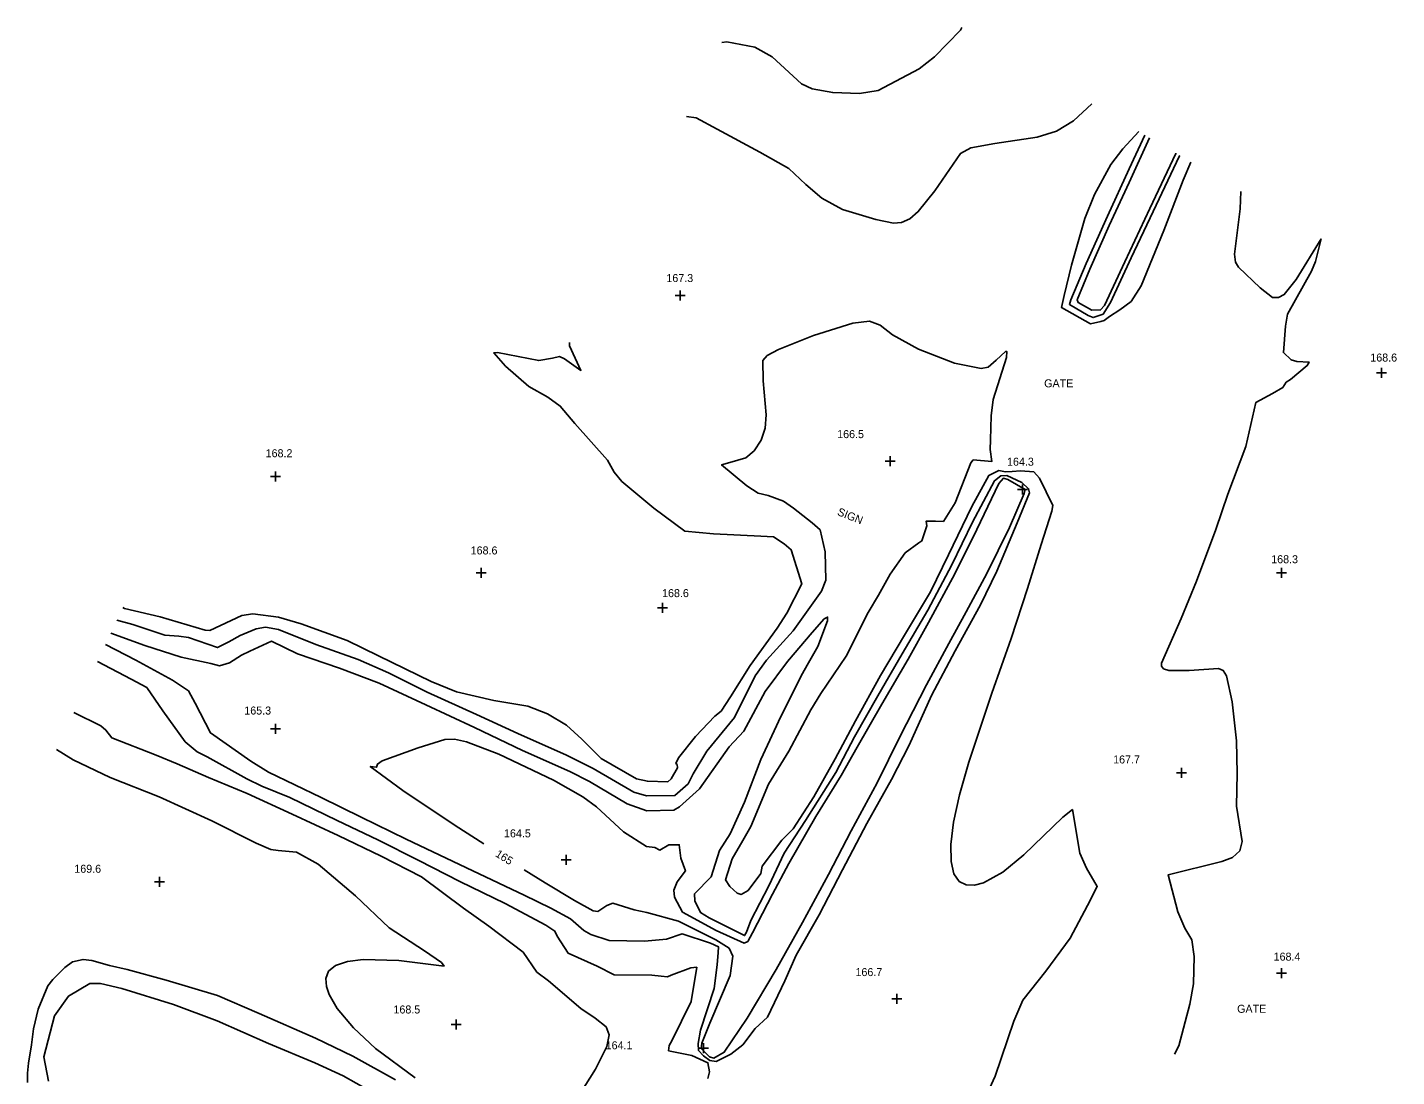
# Model space of a CAD drawing. Extents: x 1475150 to 2003689, y 770235 to 1112803.
# Drawn here: x 1998361.6 to 1998703.8, y 775974.1 to 776236.3 of the extents above; entities that cross this region are included whole.
import ezdxf

# ---------------------------------------------------------------- set-up
doc = ezdxf.new("R2010")
doc.units = 0
for name, color, linetype in [('RD_DTM_Major1', 7, 'Continuous'), ('RD_DTM_Major1_Lbl', 7, 'Continuous'), ('RD_DTM_Minor1', 7, 'Continuous'), ('RD_DTM_Spot_Elev', 7, 'Continuous'), ('RD_TX_Misc1', 7, 'Continuous')]:
    doc.layers.add(name, color=color, linetype=linetype)

msp = doc.modelspace()

# ---------------------------------------------------------------- linework, layer by layer
at = {"layer": 'RD_DTM_Major1'}
for points in [[(1998648.62, 776204.85), (1998648.6, 776204.79), (1998642.14, 776191.04), (1998635.9, 776177.72), (1998630.82, 776166.81), (1998629.82, 776165.7), (1998627.6, 776165.64), (1998624.19, 776167.53), (1998623.96, 776168.27), (1998627.13, 776175.87), (1998631.95, 776186.84), (1998636.92, 776197.58), (1998642.08, 776208.7)], [(1998475.7, 776032.25), (1998468.54, 776036.9), (1998455.5, 776045.62), (1998447.33, 776051.58), (1998448.89, 776051.43), (1998449.14, 776052.2), (1998450.32, 776053.04), (1998459.28, 776056.24), (1998465.94, 776058.38), (1998468.33, 776058.41), (1998471.34, 776057.8), (1998479.42, 776054.67), (1998493.08, 776048.2), (1998500.43, 776044.04), (1998503.82, 776041.52), (1998510.62, 776035.25), (1998516.31, 776031.59), (1998518.41, 776031.35), (1998519.67, 776030.71), (1998521.89, 776032.04), (1998524.55, 776032.07), (1998524.95, 776028.74), (1998526.06, 776025.56), (1998524.04, 776022.81), (1998523.17, 776020.7), (1998523.38, 776018.97), (1998525.35, 776015.23), (1998533.78, 776010.66), (1998540.74, 776007.44), (1998541.63, 776007.87), (1998542.86, 776010.06), (1998547.82, 776019.73), (1998551.89, 776027.38), (1998558.68, 776039.14), (1998565.03, 776049.36), (1998569.03, 776056.41), (1998575.15, 776067.23), (1998581.73, 776078.46), (1998586.81, 776087.57), (1998593.37, 776099.76), (1998598.93, 776110.84), (1998604.36, 776122.36), (1998605.56, 776123.7), (1998606.61, 776123.36), (1998610.94, 776120.82), (1998610.72, 776119.86), (1998607.05, 776111.33), (1998601.39, 776099.81), (1998596.27, 776090.25), (1998591.93, 776082.35), (1998586.31, 776072), (1998579.67, 776059.04), (1998573.96, 776047.49), (1998567.53, 776035.52), (1998561.84, 776024.66), (1998555.31, 776012.65), (1998548.74, 776000.91), (1998541.51, 775988.73), (1998535.79, 775980.2), (1998533.2, 775978.72), (1998532.1, 775979.05), (1998529.97, 775981.17), (1998530.14, 775982.49), (1998532.18, 775987.43), (1998537.29, 775999.36), (1998537.95, 776004.23), (1998537.01, 776006.2), (1998533.66, 776008.31), (1998524.35, 776012.93), (1998516.41, 776015.13), (1998513.24, 776015.79), (1998507.93, 776017.46), (1998506.41, 776016.85), (1998504.2, 776015.35), (1998503.05, 776015.58), (1998498.32, 776018.09), (1998491, 776022.53), (1998485.81, 776025.79)]]:
    msp.add_lwpolyline(points, dxfattribs=at)
at = {"layer": 'RD_DTM_Minor1'}
for points in [[(1998535.18, 776232.58), (1998536.43, 776232.68), (1998543.45, 776231.35), (1998547.74, 776228.94), (1998555.04, 776222.21), (1998557.71, 776220.97), (1998562.91, 776220.01), (1998569.54, 776219.8), (1998574.28, 776220.58), (1998584.49, 776225.99), (1998588.32, 776228.96), (1998594.78, 776235.61), (1998595.16, 776236.32)], [(1998526.35, 776214.04), (1998528.75, 776213.76), (1998534.04, 776210.87), (1998544.71, 776205.1), (1998551.92, 776201.03), (1998556.19, 776197.1), (1998560.18, 776193.61), (1998565.31, 776190.78), (1998573.62, 776188.32), (1998578.09, 776187.41), (1998580.11, 776187.59), (1998582.14, 776188.51), (1998584.26, 776190.31), (1998588.39, 776195.44), (1998594.81, 776204.81), (1998597.4, 776206.22), (1998603.4, 776207.28), (1998614.01, 776208.91), (1998618.79, 776210.41), (1998623.09, 776212.97), (1998627.67, 776217.18)], [(1998652.38, 776202.64), (1998650.49, 776198.11), (1998645.63, 776185.6), (1998639.97, 776171.73), (1998637.44, 776167.79), (1998634.59, 776165.71), (1998632.02, 776164.11), (1998630.7, 776163.05), (1998629.92, 776162.79), (1998627.28, 776162.25), (1998620.06, 776166.28), (1998620.68, 776169.32), (1998622.54, 776176.89), (1998625.87, 776188.54), (1998628.29, 776194.55), (1998632.39, 776202.07), (1998635.41, 776205.98), (1998639.39, 776210.28)], [(1998649.59, 776204.27), (1998649.55, 776204.19), (1998642.92, 776190.34), (1998637.49, 776178.7), (1998632.32, 776167.54), (1998630.46, 776164.63), (1998628, 776163.79), (1998626.68, 776164.3), (1998622.04, 776167.03), (1998622.35, 776168.23), (1998626.24, 776177.31), (1998631.51, 776189.16), (1998636.93, 776200.95), (1998640.89, 776209.4)], [(1998664.86, 776195.29), (1998664.71, 776190.95), (1998663.26, 776179.63), (1998663.53, 776177.64), (1998664.27, 776176.39), (1998669.67, 776171.26), (1998672.77, 776168.86), (1998674.26, 776168.78), (1998675.72, 776169.54), (1998678.71, 776173.29), (1998684.91, 776183.48)], [(1998684.94, 776183.47), (1998683.56, 776177.78), (1998682.54, 776175.37), (1998676.54, 776164.67), (1998676.05, 776161.68), (1998675.5, 776155.05), (1998677.44, 776153.23), (1998678.87, 776152.8), (1998681.92, 776152.68), (1998681.47, 776151.79), (1998677.29, 776148.31), (1998676.21, 776147.65), (1998675.4, 776146.33), (1998672.74, 776144.81), (1998668.64, 776142.62), (1998666.15, 776131.57), (1998661.63, 776119.7), (1998658.62, 776110.85), (1998653.78, 776097.97), (1998649.95, 776088.57), (1998645.06, 776077.46), (1998645.05, 776076.66), (1998645.56, 776075.99), (1998646.85, 776075.57), (1998651.93, 776075.64), (1998659.28, 776076.12), (1998660.49, 776075.61), (1998661.31, 776074.25), (1998662.66, 776067.81), (1998663.8, 776058.05), (1998663.97, 776049.86), (1998663.8, 776041.71), (1998665.23, 776032.9), (1998664.59, 776030.55), (1998662.78, 776028.89), (1998660.14, 776027.84), (1998646.67, 776024.52), (1998649.14, 776015.28), (1998650.85, 776011.25), (1998652.6, 776008.26), (1998653.22, 776004.11), (1998653.07, 775997.32), (1998652.08, 775992.21), (1998649.37, 775981.83), (1998648.28, 775979.75)], [(1998383.97, 776088.16), (1998387.97, 776087.12), (1998395.98, 776084.47), (1998399.46, 776084.18), (1998401.92, 776083.81), (1998409.14, 776081.35), (1998411.94, 776082.79), (1998414.79, 776084.39), (1998418.83, 776086), (1998421.17, 776086.42), (1998424.36, 776085.82), (1998433.69, 776082.09), (1998444.27, 776078.34), (1998451.86, 776075), (1998461.54, 776070.21), (1998473.85, 776064.61), (1998484.22, 776059.86), (1998496.35, 776054.41), (1998503.02, 776051.13), (1998513.22, 776045.19), (1998516.32, 776044.26), (1998523.4, 776044.35), (1998526.78, 776047.29), (1998528.04, 776049.75), (1998531.41, 776055.41), (1998538.35, 776063.82), (1998543.5, 776074.28), (1998546.33, 776078.21), (1998553.01, 776085.55), (1998560.07, 776095.39), (1998561.13, 776098.15), (1998561.01, 776105.28), (1998559.76, 776110.73), (1998557.76, 776112.48), (1998553.1, 776116.18), (1998550.56, 776117.95), (1998546.74, 776119.37), (1998544.29, 776119.96), (1998541.43, 776121.73), (1998535.13, 776127), (1998537.17, 776127.6), (1998541.13, 776128.79), (1998543.24, 776130.52), (1998544.97, 776133.16), (1998545.99, 776136.18), (1998546.24, 776139.53), (1998545.51, 776147.99), (1998545.4, 776153.06), (1998546.54, 776154.36), (1998549.31, 776155.85), (1998558.11, 776159.31), (1998567.87, 776162.42), (1998572.08, 776162.93), (1998574.76, 776161.93), (1998577.8, 776159.48), (1998584.31, 776155.89), (1998593.34, 776152.4), (1998599.94, 776151.08), (1998601.7, 776151.42), (1998603.7, 776153.13), (1998606.02, 776155.29), (1998606.43, 776155.31), (1998606.31, 776153.83), (1998602.95, 776143.3), (1998602.45, 776139.22), (1998602.32, 776133.25), (1998602.26, 776130.84), (1998602.62, 776127.8), (1998597.99, 776128.28), (1998597.41, 776127.54), (1998593.45, 776117.52), (1998590.55, 776112.87), (1998588.59, 776112.89), (1998586.2, 776112.89), (1998586.38, 776111.72), (1998585.14, 776107.97), (1998584.43, 776107.51), (1998581, 776105.02), (1998577.2, 776099.69), (1998574.29, 776094.47), (1998571.71, 776090.1), (1998566.27, 776079.22), (1998559.88, 776069.88), (1998557.38, 776065.79), (1998551.93, 776055.41), (1998546.8, 776047.19), (1998542.4, 776036.66), (1998540.4, 776033.08), (1998537.78, 776028.55), (1998536.11, 776023.25), (1998537.15, 776021.66), (1998539.03, 776019.94), (1998540.02, 776019.63), (1998541.72, 776020.65), (1998544.9, 776024.86), (1998545.25, 776026.73), (1998550.18, 776033.2), (1998552.98, 776036.07), (1998558.18, 776044.07), (1998563.48, 776053.54), (1998568.57, 776063.04), (1998574.86, 776074.32), (1998580.79, 776084.44), (1998587.32, 776095.3), (1998591.82, 776104.51), (1998597.64, 776116.57), (1998601.86, 776124.35), (1998604.4, 776125.56), (1998606.09, 776125.24), (1998607.74, 776125.37), (1998609.82, 776125.47), (1998613.14, 776125.22), (1998614.58, 776123.63), (1998617.91, 776116.88), (1998617.66, 776115.46), (1998614.95, 776107.13), (1998611.56, 776096.09), (1998607.46, 776083.56), (1998602.68, 776069.97), (1998596.88, 776052.7), (1998594.55, 776044.57), (1998593.05, 776037.69), (1998592.37, 776032.14), (1998592.44, 776027.87), (1998593.17, 776024.82), (1998594.48, 776022.91), (1998596.24, 776022.01), (1998598.33, 776021.94), (1998600.6, 776022.54), (1998605.4, 776025.24), (1998610.61, 776029.52), (1998620.39, 776038.98), (1998622.79, 776040.86), (1998624.65, 776029.92), (1998626.28, 776026.24), (1998628.99, 776021.65), (1998626.57, 776016.84), (1998622.21, 776008.72), (1998616.14, 776000.43), (1998610.35, 775993.21), (1998608.14, 775988), (1998603.45, 775974.21), (1998597.89, 775962.07)], [(1998385.47, 776091.37), (1998385.92, 776091.12), (1998394.85, 776089.05), (1998406.07, 776085.68), (1998407.25, 776085.58), (1998415.24, 776089.35), (1998417.97, 776089.75), (1998424.36, 776088.94), (1998430.07, 776087.25), (1998441.52, 776083.11), (1998449.4, 776079.31), (1998462.56, 776072.89), (1998468.88, 776070.26), (1998478.18, 776068.11), (1998486.68, 776066.71), (1998491.57, 776064.81), (1998496.39, 776061.92), (1998500.18, 776058.45), (1998505.04, 776053.65), (1998513.85, 776048.57), (1998516.57, 776047.92), (1998521.66, 776047.81), (1998522.52, 776048.55), (1998524.07, 776051.25), (1998524, 776052.1), (1998523.64, 776052.4), (1998524.38, 776053.79), (1998528.58, 776059.08), (1998533.45, 776064.19), (1998534.97, 776065.46), (1998537.31, 776069.04), (1998542.24, 776076.85), (1998548.98, 776086.18), (1998551.44, 776089.97), (1998555.15, 776097.25), (1998552.49, 776105.77), (1998550.75, 776107.25), (1998548.07, 776108.98), (1998544.93, 776109.2), (1998533.11, 776109.74), (1998525.94, 776110.39), (1998518.16, 776116.17), (1998510.2, 776122.84), (1998508.27, 776125.19), (1998506.63, 776128.13), (1998498.44, 776137.36), (1998494.8, 776141.67), (1998491.69, 776143.93), (1998486.94, 776146.57), (1998481.13, 776151.63), (1998478.16, 776154.99), (1998479.11, 776155.06), (1998489.44, 776153.05), (1998492.86, 776153.67), (1998494.65, 776154.1), (1998495.89, 776153.48), (1998499.98, 776150.59), (1998497.12, 776156.76), (1998497.08, 776157.56)], [(1998382.48, 776084.96), (1998390.98, 776081.83), (1998400.08, 776078.93), (1998407.45, 776077.33), (1998409.62, 776076.73), (1998412.16, 776077.5), (1998415.11, 776079.41), (1998417.24, 776080.41), (1998422.62, 776082.94), (1998429.18, 776079.77), (1998439.67, 776076.17), (1998449.55, 776072.45), (1998461.23, 776067.06), (1998473.37, 776061.35), (1998485.39, 776055.58), (1998497.22, 776050.39), (1998502.11, 776047.9), (1998511.49, 776042.28), (1998516.41, 776040.5), (1998523.18, 776040.74), (1998524.57, 776041.55), (1998529.57, 776046.07), (1998537.03, 776056.55), (1998540.63, 776060.45), (1998545.97, 776070.38), (1998551.55, 776077.84), (1998557.71, 776085.13), (1998560.75, 776088.53), (1998561.6, 776088.97), (1998561.61, 776088.02), (1998559.14, 776081.62), (1998556.51, 776076.94), (1998555.31, 776074.85), (1998549.94, 776064.11), (1998544.96, 776053.39), (1998540.86, 776042.7), (1998537.23, 776034.79), (1998534.57, 776030.66), (1998532.51, 776024.07), (1998528.32, 776019.76), (1998528.39, 776018.08), (1998529.86, 776015.12), (1998532, 776013.77), (1998540.87, 776009.37), (1998541.35, 776010.19), (1998542.45, 776013.13), (1998546.91, 776021.8), (1998550.73, 776029.98), (1998556.1, 776038.11), (1998563.64, 776050.09), (1998568.35, 776059), (1998574.14, 776069.3), (1998580.2, 776079.73), (1998586.62, 776090.65), (1998592.61, 776102.03), (1998597.79, 776112.67), (1998603.31, 776123.02), (1998604.86, 776124.24), (1998606.4, 776124.3), (1998610.15, 776122.59), (1998611.81, 776121.01), (1998612.09, 776120), (1998609, 776112.5), (1998603.92, 776100.46), (1998599.82, 776092), (1998593.46, 776080.53), (1998587.58, 776069.33), (1998581.95, 776056.98), (1998577.59, 776048.36), (1998571.44, 776037.36), (1998565.3, 776025.83), (1998559.49, 776014.57), (1998553.78, 776004.48), (1998550.89, 775998.09), (1998546.56, 775988.98), (1998543.52, 775986.14), (1998540.43, 775982.07), (1998537.4, 775979.7), (1998533.79, 775977.92), (1998532.17, 775978.16), (1998530.62, 775979.27), (1998529.35, 775980.68), (1998529.29, 775982.43), (1998529.87, 775985.68), (1998533.26, 775996.16), (1998534.04, 776002.06), (1998534.28, 776005.11), (1998534.31, 776006.58), (1998532.31, 776007.45), (1998525.24, 776009.83), (1998521.37, 776008.43), (1998515.81, 776008), (1998507, 776008.1), (1998502.46, 776009.64), (1998500.66, 776010.62), (1998497.37, 776013.56), (1998492.45, 776016.24), (1998485.78, 776019.44), (1998472.96, 776025.5), (1998456.31, 776033.42), (1998445.07, 776038.95), (1998435.08, 776043.86), (1998421.89, 776050.18), (1998417.48, 776052.91), (1998407.41, 776060.02), (1998403.53, 776067.41), (1998401.94, 776070.51), (1998397.94, 776073.22), (1998388.76, 776078.18), (1998381.15, 776082.1)], [(1998531.71, 775973.61), (1998532.11, 775975.33), (1998531.68, 775977.56), (1998527.66, 775979.43), (1998521.88, 775980.57), (1998522, 775981.85), (1998522.72, 775983.09), (1998527.5, 775992.86), (1998528.92, 776001.43), (1998527.44, 776001.26), (1998522.53, 775999.47), (1998521.59, 775999.05), (1998520.02, 775999.2), (1998517.7, 775999.49), (1998508.25, 775999.59), (1998504.01, 776001.69), (1998496.75, 776004.98), (1998494.06, 776009.18), (1998493.45, 776010.49), (1998491.19, 776011.98), (1998480.99, 776017.37), (1998469.7, 776022.84), (1998459.48, 776028.13), (1998449.18, 776033.3), (1998439.03, 776038.14), (1998427.26, 776043.87), (1998420.23, 776046.74), (1998416.45, 776048.5), (1998406.6, 776054.04), (1998404.06, 776055.31), (1998401.09, 776057.75), (1998395.46, 776065.51), (1998391.48, 776071.36), (1998387.59, 776073.44), (1998379.17, 776077.87)], [(1998497.36, 775966.06), (1998503.6, 775975.95), (1998506.46, 775981.63), (1998507.01, 775984.53), (1998506.3, 775986.54), (1998503.49, 775988.75), (1998499.91, 775991.17), (1998491.87, 775998.09), (1998488.96, 776000.22), (1998485.53, 776005.21), (1998476.99, 776011.74), (1998470.59, 776016.2), (1998460.14, 776024.05), (1998450.04, 776029.21), (1998439.27, 776034.33), (1998427.8, 776039.71), (1998416.58, 776044.85), (1998406.89, 776048.87), (1998399.05, 776052.31), (1998393.84, 776054.42), (1998382.72, 776058.78), (1998381.26, 776060.7), (1998379.97, 776061.78), (1998373.25, 776065.15)], [(1998458.56, 775973.85), (1998448.62, 775981.1), (1998443.14, 775986.29), (1998439.07, 775991.1), (1998437.01, 775994.63), (1998436.37, 775996.62), (1998436.25, 775998.61), (1998436.92, 776000.43), (1998438.66, 776001.91), (1998441.63, 776002.89), (1998445.53, 776003.39), (1998454.47, 776003.16), (1998465.75, 776001.75), (1998465.14, 776002.61), (1998460.91, 776005.52), (1998452.01, 776011.28), (1998443.67, 776019.28), (1998434.31, 776027.24), (1998428.93, 776030.22), (1998424.33, 776030.59), (1998422.47, 776030.91), (1998418.8, 776032.49), (1998407.74, 776038.02), (1998394.57, 776044), (1998382.35, 776048.83), (1998373.05, 776053.3), (1998368.93, 776055.87)], [(1998361.66, 775972.62), (1998361.64, 775974.97), (1998361.89, 775977.48), (1998362.64, 775982.08), (1998363.21, 775986.05), (1998364.32, 775990.95), (1998366.74, 775996.83), (1998367.98, 775998.4), (1998371, 776001.4), (1998372.92, 776002.83), (1998375.57, 776003.42), (1998377.72, 776003.17), (1998382.2, 776001.92), (1998386.55, 776000.9), (1998396.32, 775998.25), (1998409.13, 775994.35), (1998419.53, 775989.87), (1998433.65, 775983.74), (1998443, 775979.22), (1998453.61, 775973.3)], [(1998366.94, 775972.99), (1998365.72, 775979.04), (1998368.45, 775989.32), (1998371.91, 775994.22), (1998377.23, 775997.37), (1998379.92, 775997.36), (1998385.23, 775996.17), (1998398.17, 775992.14), (1998409.07, 775988.02), (1998421.88, 775982.42), (1998433.5, 775977.55), (1998440.56, 775974.3), (1998447.08, 775970.63)]]:
    msp.add_lwpolyline(points, dxfattribs=at)
at = {"layer": 'RD_DTM_Spot_Elev'}
for p, q in [((1998523.49, 776169.3), (1998525.99, 776169.3)), ((1998524.74, 776168.05), (1998524.74, 776170.55)), ((1998700, 776148.75), (1998700, 776151.25)), ((1998698.75, 776150), (1998701.25, 776150)), ((1998575.97, 776127.9), (1998578.47, 776127.9)), ((1998577.22, 776126.65), (1998577.22, 776129.15)), ((1998422.36, 776124.12), (1998424.86, 776124.12)), ((1998423.61, 776122.87), (1998423.61, 776125.37)), ((1998609.04, 776120.83), (1998611.54, 776120.83)), ((1998610.29, 776119.58), (1998610.29, 776122.08)), ((1998473.75, 776100), (1998476.25, 776100)), ((1998475, 776098.75), (1998475, 776101.25)), ((1998673.75, 776100), (1998676.25, 776100)), ((1998675, 776098.75), (1998675, 776101.25)), ((1998520.36, 776090.04), (1998520.36, 776092.54)), ((1998519.11, 776091.29), (1998521.61, 776091.29)), ((1998423.62, 776059.8), (1998423.62, 776062.3)), ((1998422.37, 776061.05), (1998424.87, 776061.05)), ((1998650.05, 776048.8), (1998650.05, 776051.3)), ((1998648.8, 776050.05), (1998651.3, 776050.05)), ((1998495.05, 776028.32), (1998497.55, 776028.32)), ((1998496.3, 776027.07), (1998496.3, 776029.57)), ((1998394.64, 776021.5), (1998394.64, 776024)), ((1998393.39, 776022.75), (1998395.89, 776022.75)), ((1998673.75, 776000), (1998676.25, 776000)), ((1998675, 775998.75), (1998675, 776001.25)), ((1998577.68, 775993.52), (1998580.18, 775993.52)), ((1998578.93, 775992.27), (1998578.93, 775994.77)), ((1998467.55, 775987.13), (1998470.05, 775987.13)), ((1998468.8, 775985.88), (1998468.8, 775988.38)), ((1998530.58, 775980.01), (1998530.58, 775982.51)), ((1998529.33, 775981.26), (1998531.83, 775981.26))]:
    msp.add_line(p, q, dxfattribs=at)

# ---------------------------------------------------------------- texts
at = {"layer": 'RD_DTM_Major1_Lbl'}
msp.add_text('165', height=2, rotation=327.7974, dxfattribs=at).set_placement((1998478.4, 776029.28))
at = {"layer": 'RD_DTM_Spot_Elev'}
for s, p in [('167.3', (1998521.32, 776172.68)), ('168.6', (1998697.22, 776152.81)), ('166.5', (1998564, 776133.68)), ('168.2', (1998421.18, 776128.9)), ('164.3', (1998606.44, 776126.78)), ('168.6', (1998472.41, 776104.61)), ('168.3', (1998672.46, 776102.41)), ('168.6', (1998520.24, 776093.94)), ('165.3', (1998415.85, 776064.6)), ('167.7', (1998632.96, 776052.37)), ('164.5', (1998480.74, 776033.91)), ('169.6', (1998373.37, 776025.06)), ('168.4', (1998673.06, 776003.1)), ('166.7', (1998568.57, 775999.24)), ('168.5', (1998453.12, 775989.89)), ('164.1', (1998506.14, 775980.94))]:
    msp.add_text(s, height=2, dxfattribs=at).set_placement(p)
at = {"layer": 'RD_TX_Misc1'}
for p in [(1998615.72, 776146.37), (1998663.94, 775990.06)]:
    msp.add_text('GATE', height=2, dxfattribs=at).set_placement(p)
msp.add_text('SIGN', height=2, rotation=338.45, dxfattribs=at).set_placement((1998563.87, 776114.5))

doc.saveas('drawing.dxf')
